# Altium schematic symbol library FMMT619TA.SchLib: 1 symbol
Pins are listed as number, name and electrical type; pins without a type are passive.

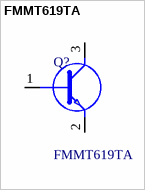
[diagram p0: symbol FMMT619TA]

## FMMT619TA
designator Q?
Diodes Inc FMMT619TA NPN Bipolar Transistor, 2 A, 50 V, 3-Pin SOT-23; Manufacturer_Name: Diodes Incorporated; Geometry.Height: 1.2mm
footprint SOT96P240X120-3N
pins: 1 B, 2 E, 3 C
